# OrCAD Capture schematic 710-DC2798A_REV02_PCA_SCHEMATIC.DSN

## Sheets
1 PAGE1: size Custom; company: ANALOG DEVICES; note: DEMO BOARD BILL OF MATERIALS; note: 60V DUAL PHASE SINGLE OUTPUT SYNCHRONOUS
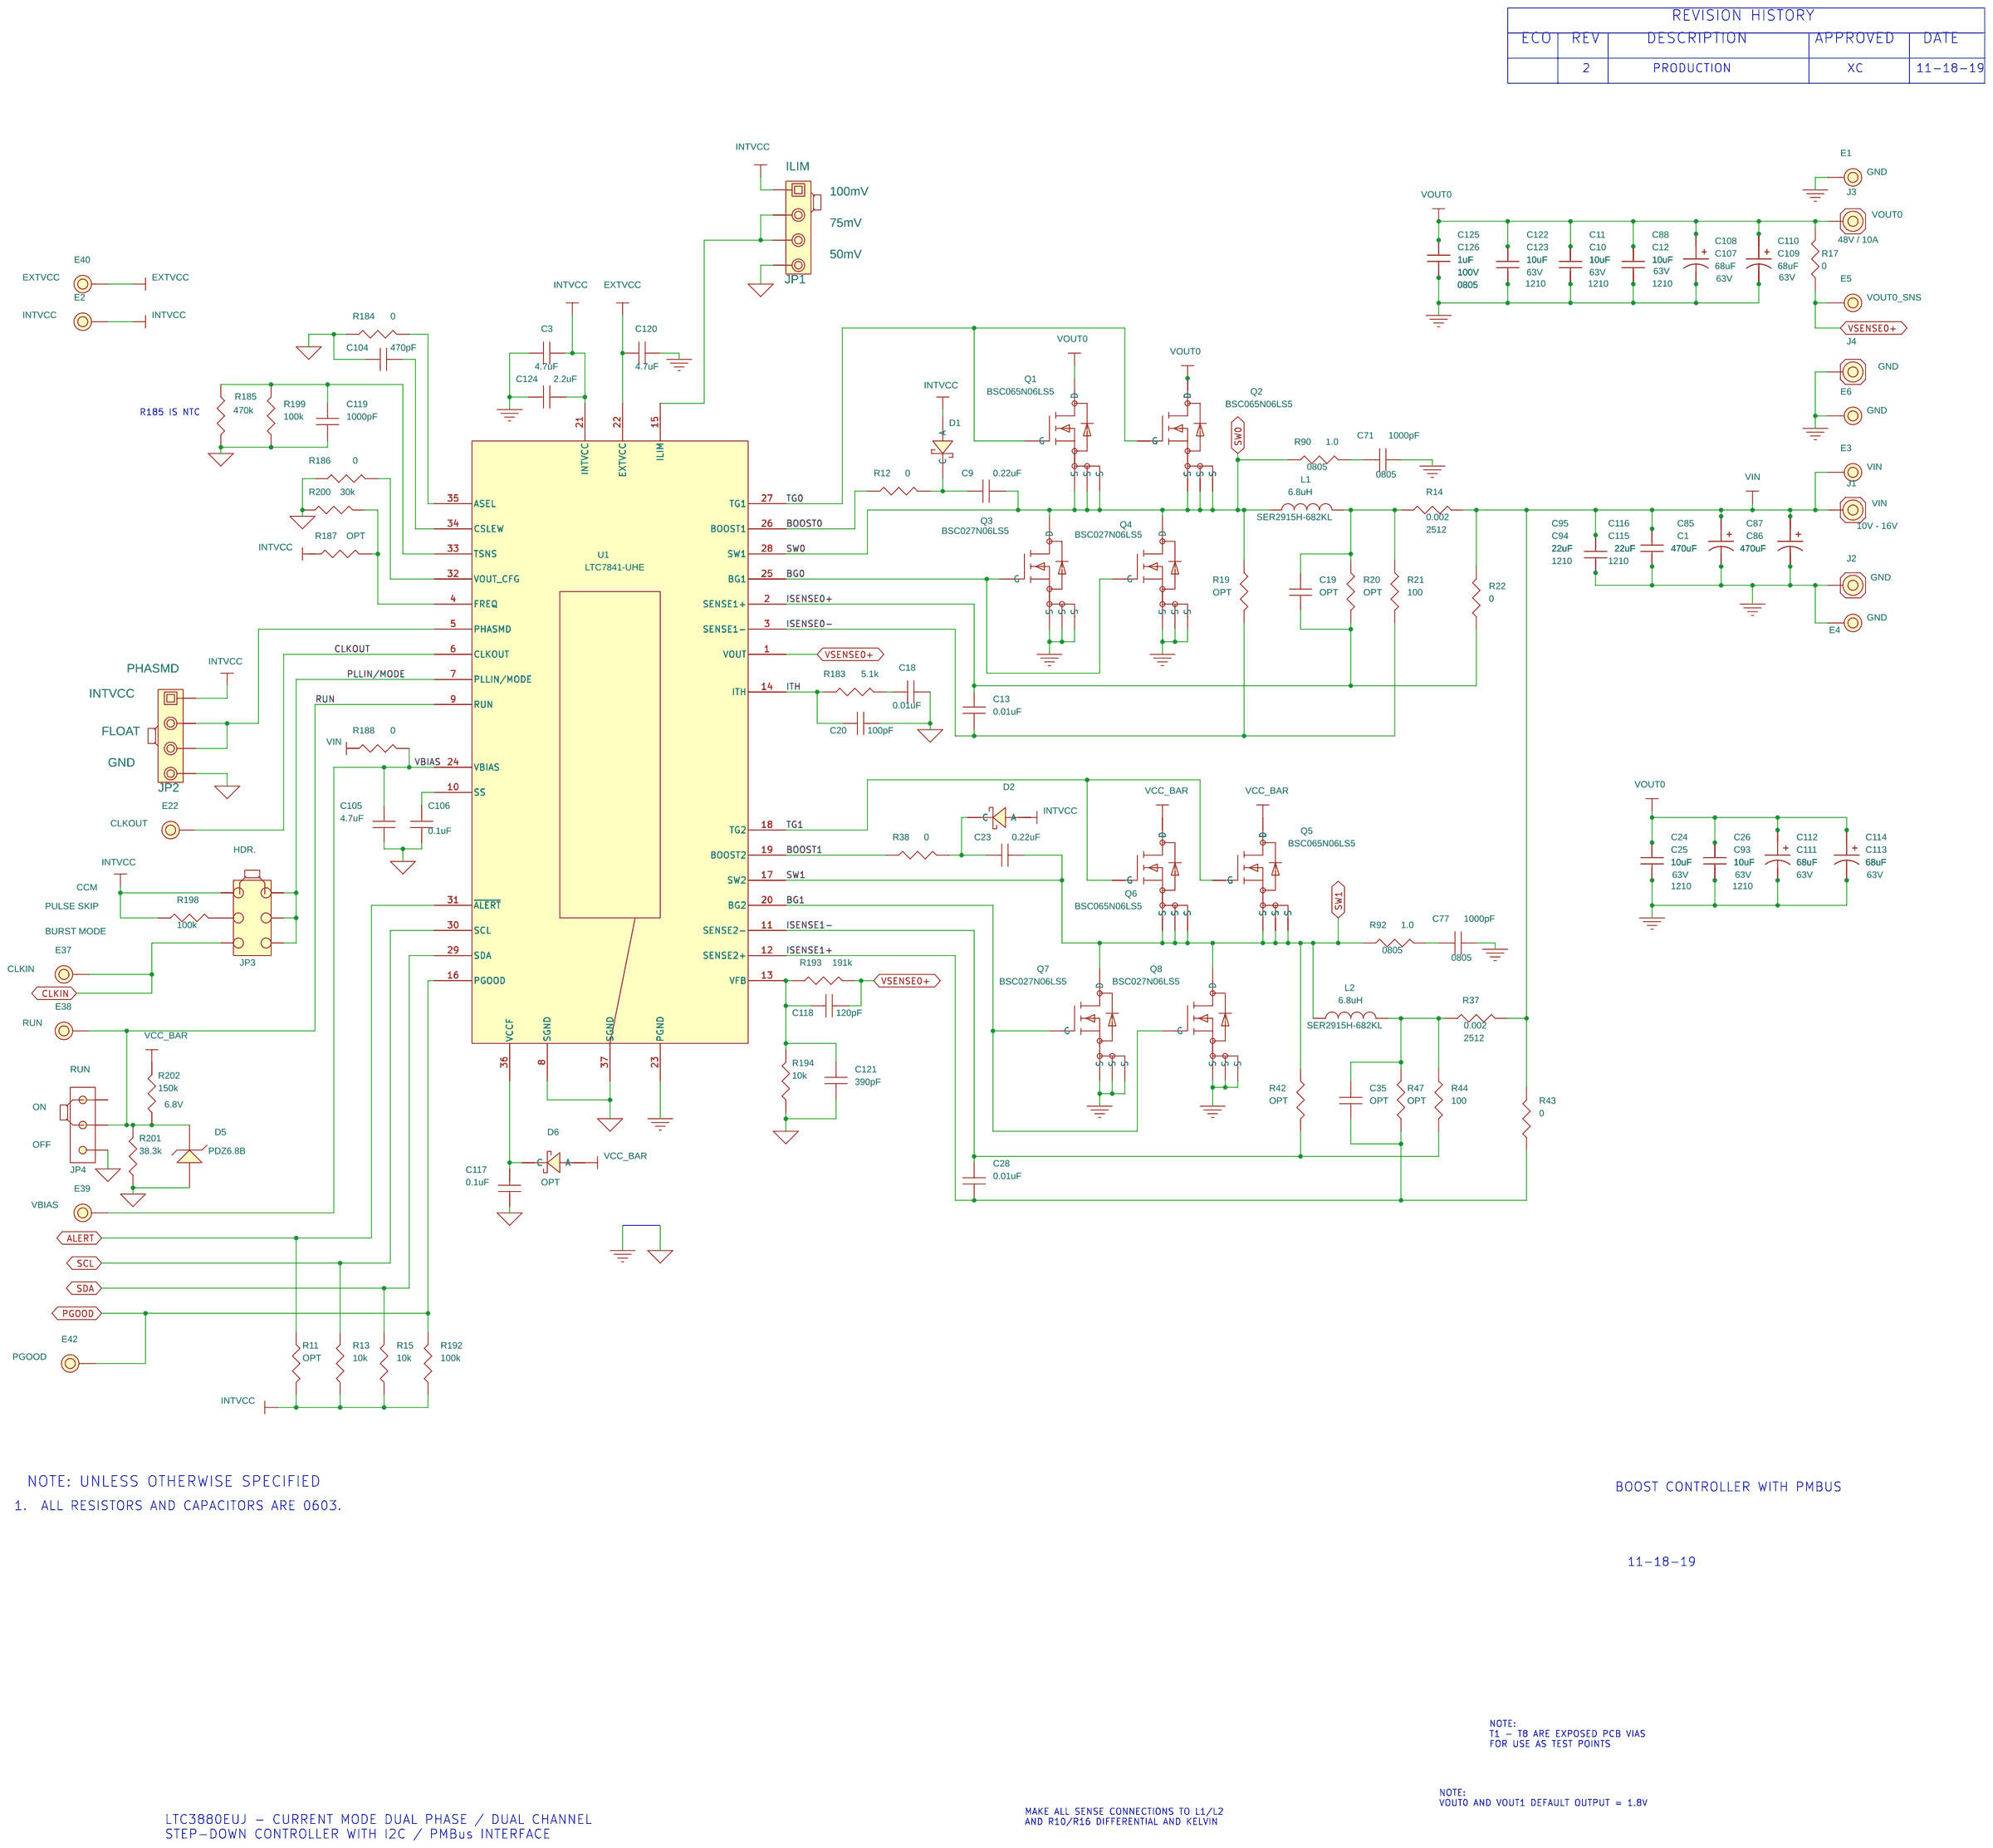
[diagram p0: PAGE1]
2 PAGE2: size Custom
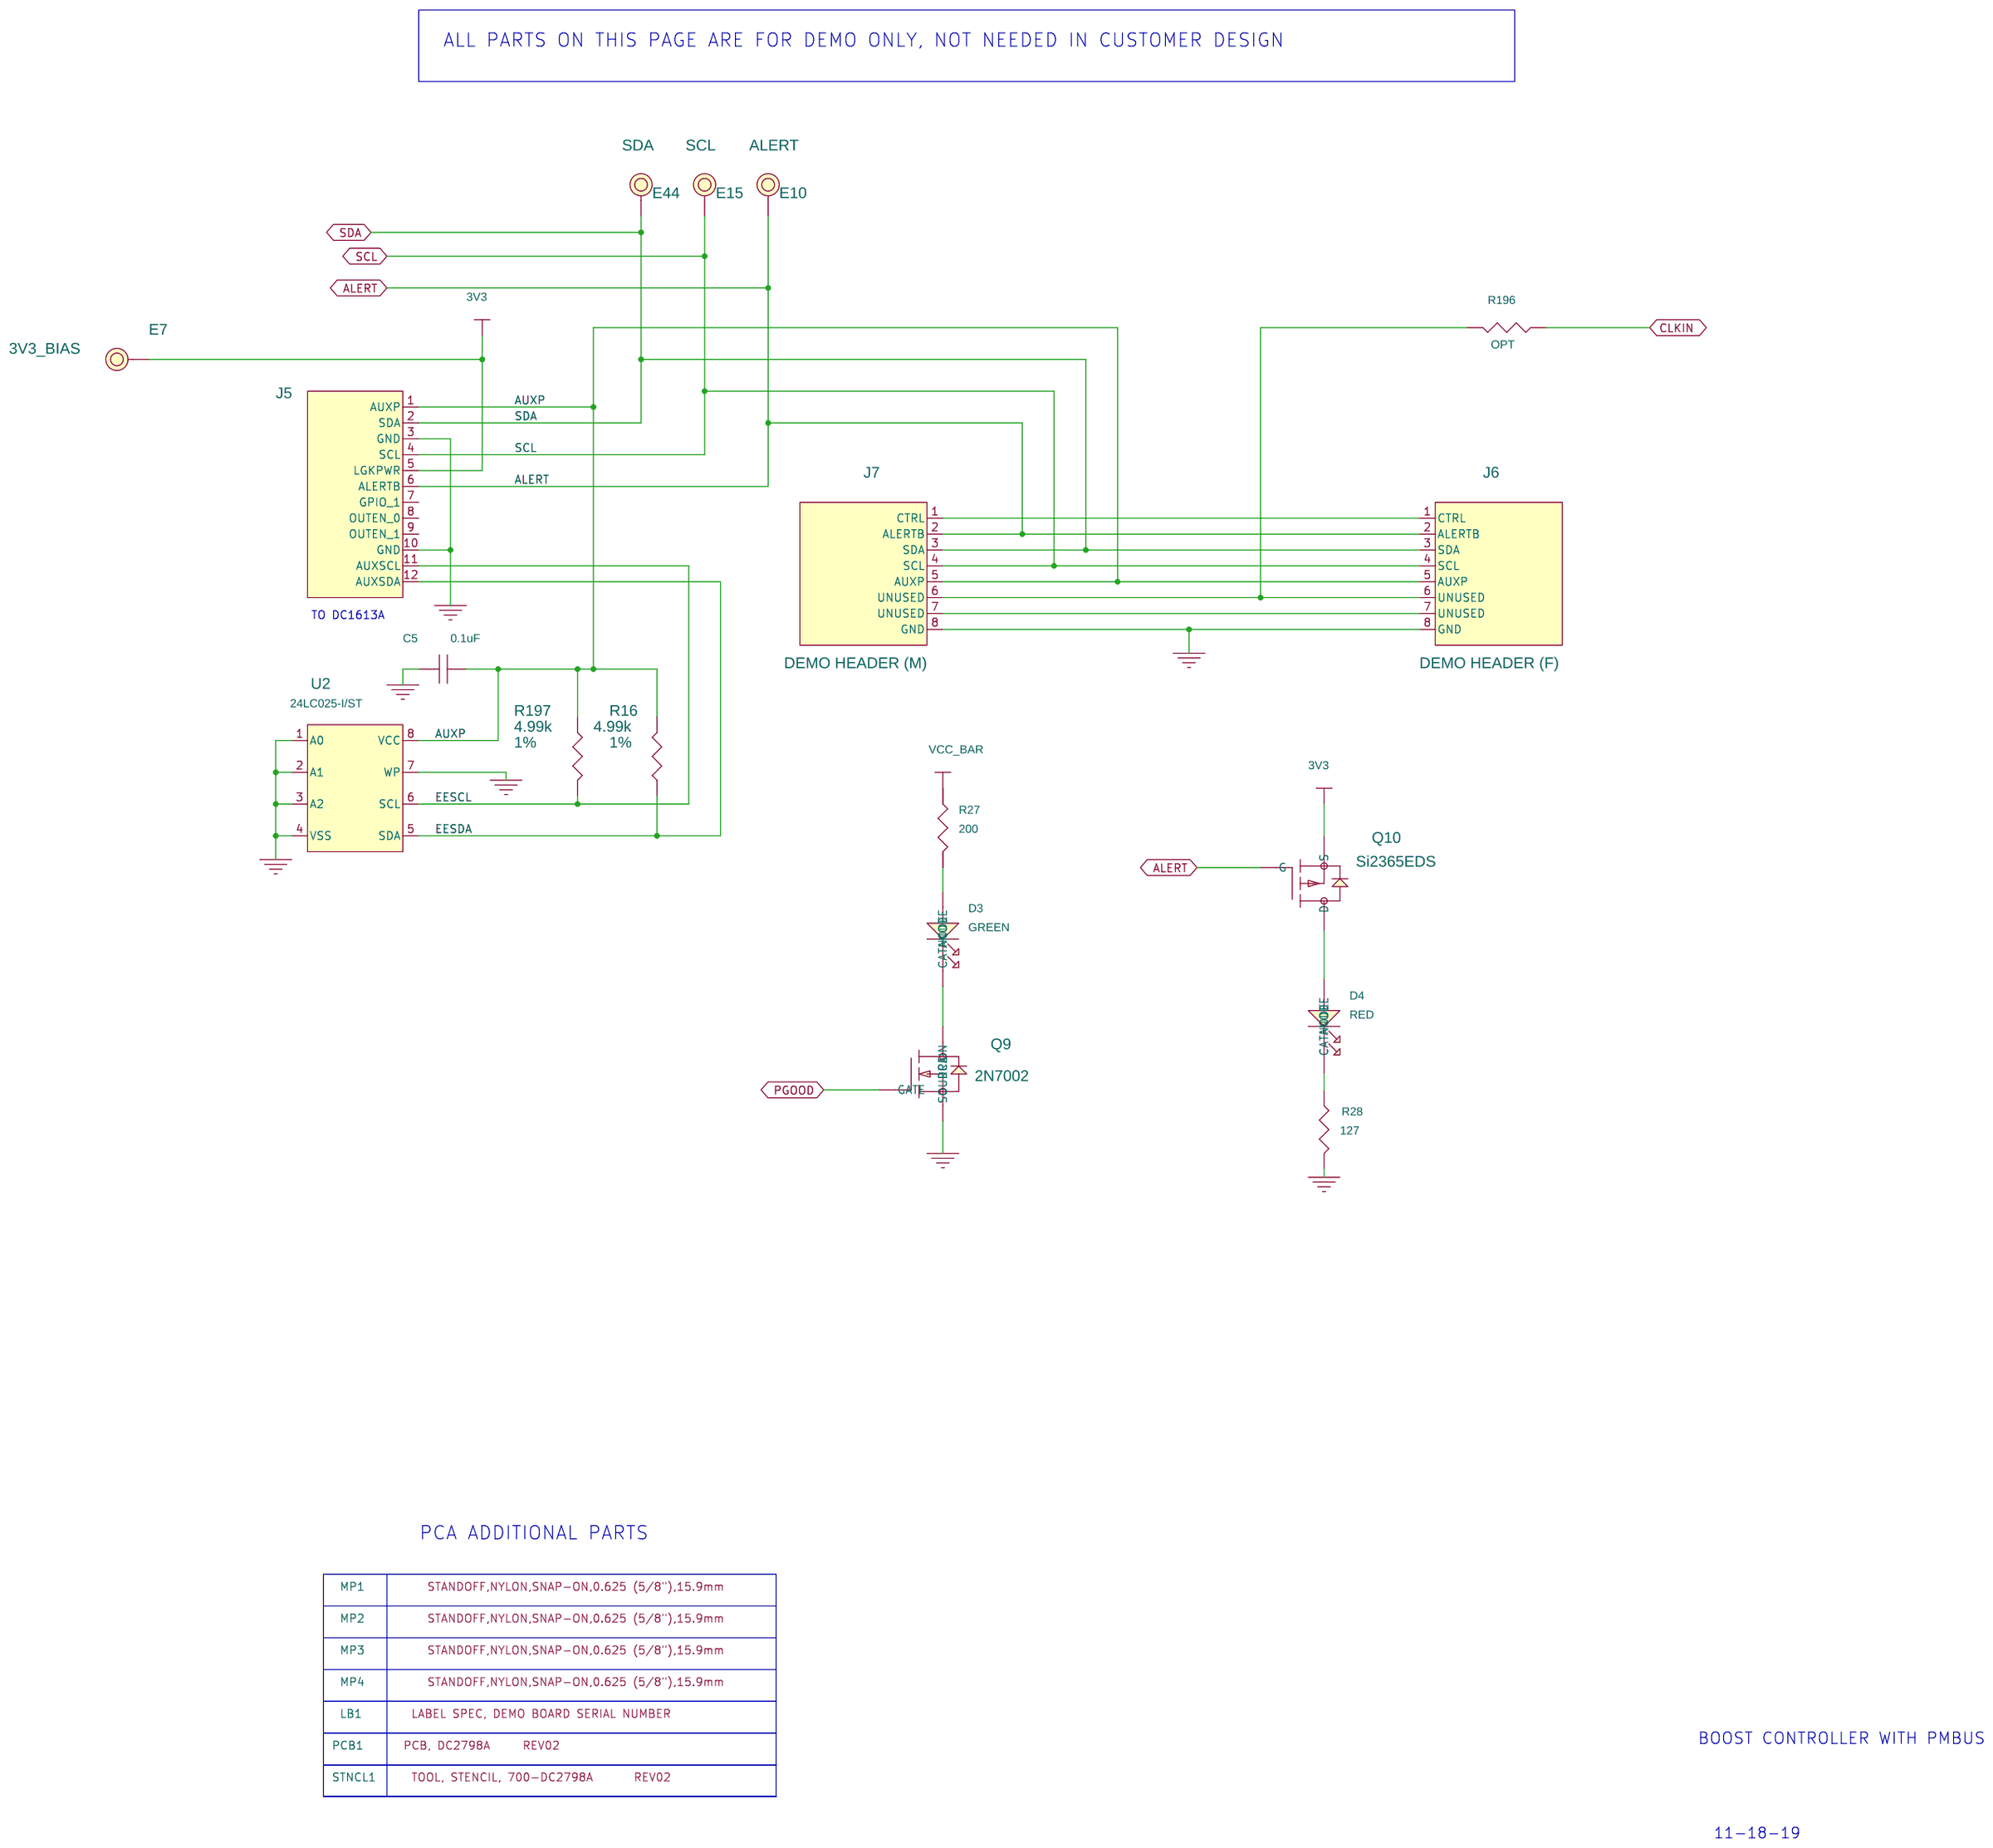
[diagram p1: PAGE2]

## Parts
sheet PAGE1
C1  470uF  [PANASONIC_ZK_10X10.2]
C3  4.7uF  [CC0603N]
C9  0.22uF  [CC0603N]
C10  10uF  [CC1210N]
C11  10uF  [CC1210N]
C12  10uF  [CC1210N]
C13  0.01uF  [CC0603N]
C18  0.01uF  [CC0603N]
C19  OPT  [CC0603N]
C20  100pF  [CC0603N]
C23  0.22uF  [CC0603N]
C24  10uF  [CC1210N]
C25  10uF  [CC1210N]
C26  10uF  [CC1210N]
C28  0.01uF  [CC0603N]
C35  OPT  [CC0603N]
C71  1000pF  [CC0805N]
C77  1000pF  [CC0805N]
C85  470uF  [PANASONIC_ZK_10X10.2]
C86  470uF  [PANASONIC_ZK_10X10.2]
C87  470uF  [PANASONIC_ZK_10X10.2]
C88  10uF  [CC1210N]
C93  10uF  [CC1210N]
C94  22uF  [CC1210N]
C95  22uF  [CC1210N]
C104  470pF  [CC0603N]
C105  4.7uF  [CC0603N]
C106  0.1uF  [CC0603N]
C107  68uF  [PANASONIC_ZC_10X10.2]
C108  68uF  [PANASONIC_ZC_10X10.2]
C109  68uF  [PANASONIC_ZC_10X10.2]
C110  68uF  [PANASONIC_ZC_10X10.2]
C111  68uF  [PANASONIC_ZC_10X10.2]
C112  68uF  [PANASONIC_ZC_10X10.2]
C113  68uF  [PANASONIC_ZC_10X10.2]
C114  68uF  [PANASONIC_ZC_10X10.2]
C115  22uF  [CC1210N]
C116  22uF  [CC1210N]
C117  0.1uF  [CC0603N]
C118  120pF  [CC0603N]
C119  1000pF  [CC0603N]
C120  4.7uF  [CC0603N]
C121  390pF  [CC0603N]
C122  10uF  [CC1210N]
C123  10uF  [CC1210N]
C124  2.2uF  [CC0603N]
C125  1uF  [CC0805N]
C126  1uF  [CC0805N]
D1  DFLS1100  [POWERDI-123]
D2  DFLS1100  [POWERDI-123]
D5  PDZ6.8B  [SOD-323N]
D6  OPT  [POWERDI-123]
E1  TEST POINT  [MILLMAX2501]
E2  TEST POINT  [MILLMAX2501]
E3  TEST POINT  [MILLMAX2501]
E4  TEST POINT  [MILLMAX2501]
E5  TEST POINT  [MILLMAX2501]
E6  TEST POINT  [MILLMAX2501]
E22  TEST POINT  [MILLMAX2501]
E37  TEST POINT  [MILLMAX2501]
E38  TEST POINT  [MILLMAX2501]
E39  TEST POINT  [MILLMAX2501]
E40  TEST POINT  [MILLMAX2501]
E42  TEST POINT  [MILLMAX2501]
J1  STUD,#10-32  [PENN-KFH-032]
J2  STUD,#10-32  [PENN-KFH-032]
J3  STUD,#10-32  [PENN-KFH-032]
J4  STUD,#10-32  [PENN-KFH-032]
JP1  HDR  [HD1X4-079]
JP2  HDR  [HD1X4-079]
JP3  HDR.  [HD2X3-079]
JP4  HDR  [HD1X3-079]
L1  6.8uH  [COILCRAFT-SER2900]
L2  6.8uH  [COILCRAFT-SER2900]
Q1  BSC065N06LS5  [INFINEON-PG-TDSON-8]
Q2  BSC065N06LS5  [INFINEON-PG-TDSON-8]
Q3  BSC027N06LS5  [INFINEON-PG-TDSON-8]
Q4  BSC027N06LS5  [INFINEON-PG-TDSON-8]
Q5  BSC065N06LS5  [INFINEON-PG-TDSON-8]
Q6  BSC065N06LS5  [INFINEON-PG-TDSON-8]
Q7  BSC027N06LS5  [INFINEON-PG-TDSON-8]
Q8  BSC027N06LS5  [INFINEON-PG-TDSON-8]
R11  OPT  [CR0603N]
R12  0  [CR0603N]
R13  10k  [CR0603N]
R14  0.002  [PANASONIC-ERJMS4S]
R15  10k  [CR0603N]
R17  0  [CR0603N]
R19  OPT  [CR0603N]
R20  OPT  [CR0603N]
R21  100  [CR0603N]
R22  0  [CR0603N]
R37  0.002  [PANASONIC-ERJMS4S]
R38  0  [CR0603N]
R42  OPT  [CR0603N]
R43  0  [CR0603N]
R44  100  [CR0603N]
R47  OPT  [CR0603N]
R90  1.0  [CR0805N]
R92  1.0  [CR0805N]
R183  5.1k  [CR0603N]
R184  0  [CR0603N]
R185  470k  [CR0805N]
R186  0  [CR0603N]
R187  OPT  [CR0603N]
R188  0  [CR0603N]
R192  100k  [CR0603N]
R193  191k  [CR0603N]
R194  10k  [CR0603N]
R198  100k  [CR0603N]
R199  100k  [CR0603N]
R200  30k  [CR0603N]
R201  38.3k  [CR0603N]
R202  150k  [CR0603N]
U1  LTC7841-UHE  [LTC-UHE-36-1876]
XJP2  SHUNT
XJP7  SHUNT
XJP8  SHUNT
XJP9  SHUNT
sheet PAGE2
C5  0.1uF  [CC0603N]
D3  GREEN  [LED_1206]
D4  RED  [LED_1206]
E7  TEST POINT  [MILLMAX2501]
E10  TEST POINT  [MILLMAX2501]
E15  TEST POINT  [MILLMAX2501]
E44  TEST POINT  [MILLMAX2501]
J5  HDR,SHROUDED  [HD2X6-079-MOLEX]
J6  HDR  [SULLINS-NPPN042FJFN-RC]
J7  HDR  [MOLEX-87760-0816]
LB1  LABEL  [895-0154_REV01]
MP1  STANDOFF  [KEYSTONE_8829-8834]
MP2  STANDOFF  [KEYSTONE_8829-8834]
MP3  STANDOFF  [KEYSTONE_8829-8834]
MP4  STANDOFF  [KEYSTONE_8829-8834]
PCB1  PCB, DC2798A
Q9  2N7002  [SOT23-3N]
Q10  Si2365EDS  [SOT23-3N]
R16  4.99k  [CR0603N]
R27  200  [CR0603N]
R28  127  [CR0603N]
R196  OPT  [CR0603N]
R197  4.99k  [CR0603N]
STNCL1  TOOL, STENCIL, 700-DC2798A
U2  24LC025-I/ST  [MICROCHIP-TSSOP-8]

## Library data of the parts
C1 C85-C87 = CAP_P: CAP.,470uF,ALUM POLY HYB,25V,20%,10x10.2mm,G,SMD,RADIAL,AEC-Q200; CLASS: DISCRETE; Dielectric Type: ALUM POLY HYB; Inventory Qty: 1000; Manufacturer: PANASONIC; Manufacturer PN: EEHZK1E471P; PART_NUMBER: 150-2512; Package Size: 10x10.2mm,G,SMD,RADIAL; Rated Voltage: 25V; Tolerance: 20%; UserField01: AEC-Q200
C3 C105 C120 = CAP: CAP.,4.7uF,X5R,25V,10%,0603; CLASS: DISCRETE; Dielectric Type: X5R; FPLIST: CC0603N,CC0603L,CC0603M; Inventory Qty: 10126; Manufacturer: MURATA; Manufacturer PN: GRM188R61E475KE15D; PART_NUMBER: 150-0445; Package Size: 0603; Rated Voltage: 25V; Tolerance: 10%
C9 C23 = CAP: CAP.,0.22uF,X7R,25V,10%,0603; CLASS: DISCRETE; Dielectric Type: X7R; FPLIST: CC0603N,CC0603L,CC0603M; Inventory Qty: 20653; Manufacturer: MURATA; Manufacturer PN: GRM188R71E224KA88D; PART_NUMBER: 150-0320; Package Size: 0603; Rated Voltage: 25V; Tolerance: 10%
C10-C12 C24-C26 C88 C93 C122 C123 = CAP: CAP.,10uF,X7R,63V,10%,1210; CLASS: DISCRETE; Component: cap; Dielectric Type: X7R; FPLIST: CC1210N,CC1210L,CC1210M; Inventory Qty: 5452; Manufacturer: Murata; Manufacturer PN: GRM32ER71J106KA12L; PART_NUMBER: 150-1321; Package Size: 1210; Part Type: CAP1210; Rated Voltage: 63V; Tolerance: 10%
C13 C28 = CAP: CAP.,0.01uF,X7R,16V,10%,0603; CLASS: DISCRETE; Component: cap; Dielectric Type: X7R; FPLIST: CC0603N,CC0603L,CC0603M; Inventory Qty: 69027; Manufacturer: AVX; Manufacturer PN: 0603YC103KAT2A; PART_NUMBER: 150-0038; Package Size: 0603; Rated Voltage: 16V; Tolerance: 10%
C18 = CAP: CAP.,0.01uF,X7R,25V,10%,0603,AEC-Q200; CLASS: DISCRETE; Component: cap; Dielectric Type: X7R; FPLIST: CC0603N,CC0603L,CC0603M; Inventory Qty: 47182; Manufacturer: AVX; Manufacturer PN: 06033C103K4Z2A; PART_NUMBER: 150-0440; Package Size: 0603; Rated Voltage: 25V; Tolerance: 10%
C19 C35 = CAP: CAP., OPTION, 0603; CLASS: DISCRETE; FPLIST: CC0603N,CC0603L,CC0603M; PART_NUMBER: 150-3038; Package Size: 0603; Package Type: SMD; UserField01: OPTION
C20 = CAP: CAP.,100pF,C0G/NP0,50V,5%,0603; CLASS: DISCRETE; Component: cap; Dielectric Type: C0G/NP0; FPLIST: CC0603N,CC0603L,CC0603M; Inventory Qty: 27408; Manufacturer: AVX; Manufacturer PN: 06035A101JAT2A; PART_NUMBER: 150-3145; Package Size: 0603; Rated Voltage: 50V; Tolerance: 5%
C71 C77 = CAP: CAP.,1000pF,C0G,100V,5%,0805; CLASS: DISCRETE; Dielectric Type: C0G; Inventory Qty: 0; Manufacturer: MURATA; Manufacturer PN: GRM2195C2A102JA01D; PART_NUMBER: 150-0816; Package Size: 0805; Package Type: SMD/SMT; Rated Voltage: 100V; Tolerance: 5%
C94 C95 C115 C116 = CAP: CAP.,22uF,X7R,25V,10%,1210; CLASS: DISCRETE; Component: cap; Dielectric Type: X7R; FPLIST: CC1210N,CC1210L,CC1210M; Inventory Qty: 4160; Manufacturer: SAMSUNG; Manufacturer PN: CL32B226KAJNNNE; PART_NUMBER: 150-3233; Package Size: 1210; Rated Voltage: 25V; Tolerance: 10%
C104 = CAP: CAP.,470pF,X7R,50V,10%,0603; CLASS: DISCRETE; Dielectric Type: X7R; FPLIST: CC0603N,CC0603L,CC0603M; Inventory Qty: 25212; Manufacturer: AVX; Manufacturer PN: 06035C471KAT2A; PART_NUMBER: 150-0125; Package Size: 0603; Rated Voltage: 50V; Tolerance: 10%; UserField01: OPTION
C106 C117 = CAP: CAP.,0.1uF,X7R,100V,10%,0603; CLASS: DISCRETE; Component: cap; Dielectric Type: X7R; FPLIST: CC0603N,CC0603L,CC0603M; Inventory Qty: 37708; Manufacturer: AVX; Manufacturer PN: 06031C104KAT2A; PART_NUMBER: 150-3294; Package Size: 0603; Rated Voltage: 100V; Tolerance: 10%
C107-C114 = CAP_P: CAP.,68uF,ALUM POLY HYB,63V,20%,10x10.2mm,G,SMD,RADIAL,AEC-Q200; CLASS: DISCRETE; Dielectric Type: ALUM POLY HYB; Inventory Qty: 4000; Manufacturer: PANASONIC; Manufacturer PN: EEHZC1J680P; PART_NUMBER: 150-2511; Package Size: 10x10.2mm,G,SMD,RADIAL; Rated Voltage: 63V; Tolerance: 20%; UserField01: AEC-Q200
C118 = CAP: CAP.,120PF,C0G/NPO,100V,5%,0603; CLASS: DISCRETE; Dielectric Type: C0G; Inventory Qty: 0; Manufacturer: AVX; Manufacturer PN: 06031A121JAT2A; PART_NUMBER: 150-0828; Package Size: 0603; Rated Voltage: 100V; Tolerance: 5%
C119 = CAP: CAP.,1000pF,X7R,16V,10%,0603; CLASS: DISCRETE; Component: cap; Dielectric Type: X7R; FPLIST: CC0603N,CC0603L,CC0603M; Inventory Qty: 1618; Manufacturer: WURTH ELEKTRONIK; Manufacturer PN: 885012206034; PART_NUMBER: 150-2357; Package Size: 0603; Rated Voltage: 16V; Tolerance: 10%
C121 = CAP: CAP.,390pF,COG/NPO,50V,5%,0603; CLASS: DISCRETE; Dielectric Type: C0G; Inventory Qty: 0; Manufacturer: AVX; Manufacturer PN: 06035A391JAT2A; PART_NUMBER: 150-0829; Package Size: 0603; Rated Voltage: 50V; Tolerance: 5%
C124 = CAP: CAP.,2.2uF,X7S,16V,10%,0603,AEC-Q200; CLASS: DISCRETE; Dielectric Type: X7S; FPLIST: CC0603N,CC0603L,CC0603M; Inventory Qty: 3469; Manufacturer: TDK; Manufacturer PN: CGA3E1X7S1C225K080AC; PART_NUMBER: 150-1663; Package Size: 0603; Package Type: Surface Mount, MLCC; Rated Voltage: 16V; Temperature Coefficient: X7S; Tolerance: 10%
C125 C126 = CAP: CAP.,1uF,X7S,100V,10%,0805; CLASS: DISCRETE; Component: cap; Dielectric Type: X7S; FPLIST: CC0805N,CC0805L,CC0805M; Inventory Qty: 17806; Manufacturer: MURATA; Manufacturer PN: GRJ21BC72A105KE11L; PART_NUMBER: 150-3382; Package Size: 0805; Rated Voltage: 100V; Tolerance: 10%
D1 D2 = DIODE_SCHOTTKY_A: DIODE,SCHOTTKY,100V,1A,POWERDI-123; CLASS: DISCRETE; Component: diode; Inventory Qty: 14646; Manufacturer: DIODES INC.; Manufacturer PN: DFLS1100-7; Max Forward Current or Rated Power: 1A; PART_NUMBER: 210-0044; Package Size: POWERDI®123; Rated Voltage: 100V; Rated Voltage or Zener Voltage: 100V
D5 = ZENER_ALT: DIODE,ZENER,6.8V,400mW,SOD-323; CLASS: DISCRETE; FPLIST: SOD-323N,SOD-323L,SOD-323M; Inventory Qty: 3630; Manufacturer: NEXPERIA; Manufacturer PN: PDZ6.8B,115; Max Forward Current or Rated Power: 400mW; PART_NUMBER: 210-0317; Package Type: SOD-323; Rated Voltage: 6.8V; Rated Voltage or Zener Voltage: 6.8V
D6 = DIODE_SCHOTTKY_A: DIODE, OPTION, SCHOTTKY, POWERDI 123; CLASS: DISCRETE; Component: diode; PART_NUMBER: 210-0341; Package Type: PowerDI 123; Rated Voltage: 100V
E1 E4 E6 = TESTPOINT_.219_MILL-MAX_2501: TEST POINT,TURRET,0.094" MTG. HOLE,PCB 0.062" THK; CLASS: IO; Inventory Qty: 416229; Manufacturer: MILL-MAX; Manufacturer PN: 2501-2-00-80-00-00-07-0; PART_FIELD_01: GND; PART_NUMBER: 260-0003
E2 = TESTPOINT_.219_MILL-MAX_2501: TEST POINT,TURRET,0.094" MTG. HOLE,PCB 0.062" THK; CLASS: IO; Inventory Qty: 416229; Manufacturer: MILL-MAX; Manufacturer PN: 2501-2-00-80-00-00-07-0; PART_FIELD_01: INTVCC; PART_NUMBER: 260-0003
E3 = TESTPOINT_.219_MILL-MAX_2501: TEST POINT,TURRET,0.094" MTG. HOLE,PCB 0.062" THK; CLASS: IO; Inventory Qty: 416229; Manufacturer: MILL-MAX; Manufacturer PN: 2501-2-00-80-00-00-07-0; PART_FIELD_01: VIN; PART_NUMBER: 260-0003
E5 = TESTPOINT_.219_MILL-MAX_2501: TEST POINT,TURRET,0.094" MTG. HOLE,PCB 0.062" THK; CLASS: IO; Inventory Qty: 416229; Manufacturer: MILL-MAX; Manufacturer PN: 2501-2-00-80-00-00-07-0; PART_FIELD_01: VOUT0_SNS; PART_NUMBER: 260-0003
E22 = TESTPOINT_.219_MILL-MAX_2501: TEST POINT,TURRET,0.094" MTG. HOLE,PCB 0.062" THK; CLASS: IO; Inventory Qty: 416229; Manufacturer: MILL-MAX; Manufacturer PN: 2501-2-00-80-00-00-07-0; PART_FIELD_01: CLKOUT; PART_NUMBER: 260-0003
E37 = TESTPOINT_.219_MILL-MAX_2501: TEST POINT,TURRET,0.094" MTG. HOLE,PCB 0.062" THK; CLASS: IO; Inventory Qty: 416229; Manufacturer: MILL-MAX; Manufacturer PN: 2501-2-00-80-00-00-07-0; PART_FIELD_01: CLKIN; PART_NUMBER: 260-0003
E38 = TESTPOINT_.219_MILL-MAX_2501: TEST POINT,TURRET,0.094" MTG. HOLE,PCB 0.062" THK; CLASS: IO; Inventory Qty: 416229; Manufacturer: MILL-MAX; Manufacturer PN: 2501-2-00-80-00-00-07-0; PART_FIELD_01: RUN; PART_NUMBER: 260-0003
E39 = TESTPOINT_.219_MILL-MAX_2501: TEST POINT,TURRET,0.094" MTG. HOLE,PCB 0.062" THK; CLASS: IO; Inventory Qty: 416229; Manufacturer: MILL-MAX; Manufacturer PN: 2501-2-00-80-00-00-07-0; PART_FIELD_01: VBIAS; PART_NUMBER: 260-0003
E40 = TESTPOINT_.219_MILL-MAX_2501: TEST POINT,TURRET,0.094" MTG. HOLE,PCB 0.062" THK; CLASS: IO; Inventory Qty: 416229; Manufacturer: MILL-MAX; Manufacturer PN: 2501-2-00-80-00-00-07-0; PART_FIELD_01: EXTVCC; PART_NUMBER: 260-0003
E42 = TESTPOINT_.219_MILL-MAX_2501: TEST POINT,TURRET,0.094" MTG. HOLE,PCB 0.062" THK; CLASS: IO; Inventory Qty: 416229; Manufacturer: MILL-MAX; Manufacturer PN: 2501-2-00-80-00-00-07-0; PART_FIELD_01: PGOOD; PART_NUMBER: 260-0003
J1 = PEM-KFH: EVAL BOARD STUD HARDWARE SET, #10-32; 10th Part Field: 10V - 16V; 11th Part Field: 11th???; 9th Part Field: VIN; CLASS: DISCRETE; Comments: CONSISTS OF QTY(1) STUD, 769-0012; QTY(1) RING LUG, 769-0013;QTY(2) HEX NUT,BRASS,761-0013; QTY(1) WASHER,#10 LOCK, 762-0021; Manufacturer: ANALOG DEVICES; Manufacturer PN: 720-0010; PART_NUMBER: 720-0010
J2 = PEM-KFH: EVAL BOARD STUD HARDWARE SET, #10-32; 10th Part Field: 5 - 24V #; 11th Part Field: 11th???; 9th Part Field: GND; CLASS: DISCRETE; Comments: CONSISTS OF QTY(1) STUD, 769-0012; QTY(1) RING LUG, 769-0013;QTY(2) HEX NUT,BRASS,761-0013; QTY(1) WASHER,#10 LOCK, 762-0021; Manufacturer: ANALOG DEVICES; Manufacturer PN: 720-0010; PART_NUMBER: 720-0010
J3 = PEM-KFH: EVAL BOARD STUD HARDWARE SET, #10-32; 10th Part Field: 48V / 10A; 11th Part Field: 11th???; 9th Part Field: VOUT0; CLASS: DISCRETE; Comments: CONSISTS OF QTY(1) STUD, 769-0012; QTY(1) RING LUG, 769-0013;QTY(2) HEX NUT,BRASS,761-0013; QTY(1) WASHER,#10 LOCK, 762-0021; Manufacturer: ANALOG DEVICES; Manufacturer PN: 720-0010; PART_NUMBER: 720-0010
J4 = PEM-KFH: EVAL BOARD STUD HARDWARE SET, #10-32; 9th Part Field: GND; CLASS: DISCRETE; Comments: CONSISTS OF QTY(1) STUD, 769-0012; QTY(1) RING LUG, 769-0013;QTY(2) HEX NUT,BRASS,761-0013; QTY(1) WASHER,#10 LOCK, 762-0021; Manufacturer: ANALOG DEVICES; Manufacturer PN: 720-0010; PART_NUMBER: 720-0010
JP1 = HDR1X4_ALT1: CONN.,HDR,MALE,1x4,2mm,VERT,ST,THT; 11th Part Field: 75mV; 12th Part Field: ILIM; 4th Part Field: 100mV; 5th Part Field: ON1_CONTROL; 9th Part Field: 50mV; CLASS: IO; FPLIST: HD1X4-079,JP4X1/079; Inventory Qty: 8742; Manufacturer: SAMTEC; Manufacturer PN: TMM-104-02-L-S; PART_NUMBER: 250-0441
JP2 = HDR1X4_ALT1: CONN.,HDR,MALE,1x4,2mm,VERT,ST,THT; 11th Part Field: FLOAT; 12th Part Field: PHASMD; 4th Part Field: GND; 5th Part Field: ON1_CONTROL; 9th Part Field: INTVCC; CLASS: IO; FPLIST: HD1X4-079,JP4X1/079; Inventory Qty: 8742; Manufacturer: SAMTEC; Manufacturer PN: TMM-104-02-L-S; PART_NUMBER: 250-0441
JP3 = HEADER_2X3_.079: CONN.,HDR.,MALE,2x3,2mm,VERT,ST,THT; CLASS: IO; Inventory Qty: 16324; L2: PULSE SKIP; L3: BURST MODE; LABEL1: CCM; Manufacturer: WURTH ELEKTRONIK; Manufacturer PN: 62000621121; PART_NUMBER: 250-0483
JP4 = 3_PIN_HEADER_.079_SINGLE_ROW_C: CONN.,HDR,MALE,1x3,2mm,VERT,ST,THT; CLASS: IO; Inventory Qty: 25420; LABEL1: RUN; LBL2: ON; LBL3: OFF; Manufacturer: Wurth Elektronik; Manufacturer PN: 62000311121; PART_NUMBER: 250-0484
L1 L2 = IND_ALT: IND.,6.8uH,Power Shielded Wirewound,10%,30A,0.00205 OHMS,27.9mm X 27.94mm; CLASS: DISCRETE; FPLIST: COILCRAFT-SER29XX-N,COILCRAFT-SER29XX-L,COILCRAFT-SER29XX-M; Inventory Qty: 0; Manufacturer: COILCRAFT; Manufacturer PN: SER2915H-682KL; PART_NUMBER: 200-0721; Package Size: 27.9mm X 27.94mm; Tolerance: 10%
Q1 Q2 Q5 Q6 = 5P_N-CH_TYPE1C: XSTR.,MOSFET, N-CH,60V,64A,PG-TDSON-8; CLASS: DISCRETE; Inventory Qty: 5800; Manufacturer: INFINEON; PART_NUMBER: 240-0322; Package Size: PG-TDSON8; Package Type: PG-TDSON-8; Rated Voltage: 60V
Q3 Q4 Q7 Q8 = 5P_N-CH_TYPE1C: XSTR.,MOSFET, N-CH,60V,100A,PG-TDSON-8; CLASS: DISCRETE; Inventory Qty: 9532; Manufacturer: INFINEON; PART_NUMBER: 240-0323; Package Size: PG-TDSON8; Package Type: PG-TDSON-8; Rated Voltage: 60V
R11 R19 R20 R42 R47 = RES: RES., OPTION, 0603; CLASS: DISCRETE; FPLIST: CR0603N,CR0603L,CR0603M; PART_NUMBER: 100-2374; Package Size: 0603
R12 R17 R22 R38 R43 R184 = RES: RES.,0 OHM,1/10W,0603,AEC-Q200; CLASS: DISCRETE; FPLIST: CR0603N,CR0603L,CR0603M; Inventory Qty: 651730; Manufacturer: VISHAY; Manufacturer PN: CRCW06030000Z0EA; PART_NUMBER: 100-0009; Package Size: 0603; Rated Power: 1/10W
R13 R15 = RES: RES.,10k OHMS,1%,1/10W,0603; CLASS: DISCRETE; FPLIST: CR0603N,CR0603L,CR0603M; Inventory Qty: 73157; Manufacturer: VISHAY; Manufacturer PN: CRCW060310K0FKEC; PART_NUMBER: 100-2532; Package Size: 0603; Part Type: CR0402; Rated Power: 1/10W; Temperature Coefficient: 100ppm/C; Tolerance: 1%
R14 R37 = RES: RES.,0.002 OHM,1%,3W,2512,METAL,SENSE,AEC-Q200; CLASS: DISCRETE; Component: res; FPLIST: CR2512N,CR2512L,CR2512M; Inventory Qty: 4000; Manufacturer: PANASONIC; Manufacturer PN: ERJMS4SF2M0U; PART_NUMBER: 100-1347; Package Size: 2512; Rated Power: 3W; Temperature Coefficient: +/-75ppm; Tolerance: 1%
R21 R44 = RES: RES.,100 OHMS,1%,1/10W,0603,AEC-Q200; CLASS: DISCRETE; Component: res; FPLIST: CR0603N,CR0603L,CR0603M; Inventory Qty: 70759; Manufacturer: PANASONIC; Manufacturer PN: ERJ3EKF1000V; PART_NUMBER: 100-2586; Package Size: 0603; Rated Power: 1/10W; Temperature Coefficient: 100ppm; Tolerance: 1%
R90 R92 = RES: RES.,1.0 OHMS,5%,1/2W,0805; CLASS: DISCRETE; Inventory Qty: 5000; Manufacturer: PANASONIC; Manufacturer PN: ERJ6DQJ1R0V; PART_NUMBER: 100-1618; Package Size: 0805; Rated Power: 1/2W; Temperature Coefficient: +/-100; Tolerance: 5%
R183 = RES: RES.,5.1k OHMS,1%,1/10W,0603,AEC-Q200; CLASS: DISCRETE; FPLIST: CR0603N,CR0603L,CR0603M; Inventory Qty: 29594; Manufacturer: NIC; Manufacturer PN: NRC06F5101TRF; PART_NUMBER: 100-0491; Package Size: 0603; Part Type: CR0402; Rated Power: 1/10W; Temperature Coefficient: 100ppm; Tolerance: 1%
R185 = RES: RES.,470k OHMS,1%,210mW,0805,NTC THERMISTOR, AEC-Q200; CLASS: DISCRETE; Inventory Qty: 4000; Manufacturer: VISHAY; Manufacturer PN: NTCS0805E3474FXT; PART_NUMBER: 100-1006; Package Size: 0805; Rated Power: 210mW; Tolerance: 1%
R186 R188 = RES: RES.,0 OHM,1/10W,0603,AEC-Q200; CLASS: DISCRETE; FPLIST: CR0603N,CR0603L,CR0603M; Inventory Qty: 651730; Manufacturer: VISHAY; Manufacturer PN: CRCW06030000Z0EA; PART_NUMBER: 100-0009; Package Size: 0603; Part Type: CR0402; Rated Power: 1/10W
R187 = RES: RES., OPTION, 0603; CLASS: DISCRETE; FPLIST: CR0603N,CR0603L,CR0603M; PART_NUMBER: 100-2374; Package Size: 0603; Part Type: CR0402
R192 = RES: RES.,100k OHMS,1%,1/10W,0603,AEC-Q200; CLASS: DISCRETE; FPLIST: CR0603N,CR0603L,CR0603M; Inventory Qty: 184622; Manufacturer: VISHAY; Manufacturer PN: CRCW0603100KFKEA; PART_NUMBER: 100-0343; Package Size: 0603; Part Type: CR0402; Rated Power: 1/10W; Temperature Coefficient: +/-100ppm; Tolerance: 1%
R193 = RES: RES.,191k OHMS,1%,1/10W,0603; CLASS: DISCRETE; FPLIST: CR0603N,CR0603L,CR0603M; Inventory Qty: 34432; Label: 0; Manufacturer: VISHAY; Manufacturer PN: CRCW0603191KFKEA; PART_NUMBER: 100-2371; Package Size: 0603; Rated Power: 1/10W; Temperature Coefficient: +/-100ppm; Tolerance: 1%
R194 = RES: RES.,10k OHMS,1%,1/10W,0603; CLASS: DISCRETE; FPLIST: CR0603N,CR0603L,CR0603M; Inventory Qty: 73157; Label: 0; Manufacturer: VISHAY; Manufacturer PN: CRCW060310K0FKEC; PART_NUMBER: 100-2532; Package Size: 0603; Rated Power: 1/10W; Temperature Coefficient: 100ppm/C; Tolerance: 1%
R198 R199 = RES: RES.,100k OHMS,1%,1/10W,0603,AEC-Q200; CLASS: DISCRETE; FPLIST: CR0603N,CR0603L,CR0603M; Inventory Qty: 184622; Manufacturer: VISHAY; Manufacturer PN: CRCW0603100KFKEA; PART_NUMBER: 100-0343; Package Size: 0603; Rated Power: 1/10W; Temperature Coefficient: +/-100ppm; Tolerance: 1%
R200 = RES: RES.,30k OHMS,1%,1/10W,0603,AEC-Q200; CLASS: DISCRETE; FPLIST: CR0603N,CR0603L,CR0603M; Inventory Qty: 19400; Manufacturer: KOA SPEER; Manufacturer PN: RK73H1JTTD3002F; PART_NUMBER: 100-2436; Package Size: 0603; Part Type: CR0402; Rated Power: 1/10W; Temperature Coefficient: 100ppm/C; Tolerance: 1%
R201 = RES: RES.,38.3k OHMS,1%,1/10W,0603,AEC-Q200; CLASS: DISCRETE; FPLIST: CR0603N,CR0603L,CR0603M; Inventory Qty: 32568; Label: 0; Manufacturer: NIC; Manufacturer PN: NRC06F3832TRF; PART_NUMBER: 100-2656; Package Size: 0603; Rated Power: 1/10W; Temperature Coefficient: 100ppm/C; Tolerance: 1%
R202 = RES: RES.,150k OHMS,1%,1/10W,0603; CLASS: DISCRETE; FPLIST: CR0603N,CR0603L,CR0603M; Inventory Qty: 37924; Label: 0; Manufacturer: PANASONIC; Manufacturer PN: ERJ3EKF1503V; PART_NUMBER: 100-2438; Package Size: 0603; Rated Power: 1/10W; Temperature Coefficient: 100ppm/C; Tolerance: 1%
U1 = LTC7841-UHE: IC,POWER CONTROLLER,QFN-36 (5x6); CLASS: IC; Inventory Qty: 0; Manufacturer: LINEAR TECH.; Manufacturer PN: LTC7841EUHE#PBF; PART_NUMBER: LTC7841EUHE#PBF; Package Size: 36QFN-5X6MM; Package Type: QFN-36 (5x6)
XJP2 XJP7-XJP9 = SHUNT_2MM: CONN.,SHUNT,FEMALE,2-POS,2mm; CLASS: IO; Inventory Qty: 84501; Manufacturer: SAMTEC; Manufacturer PN: 2SN-BK-G; PART_NUMBER: 250-0419
C5 = CAP: CAP.,0.1uF,X7R,50V,10%,0603; CLASS: DISCRETE; Dielectric Type: X7R; FPLIST: CC0603N,CC0603L,CC0603M; Inventory Qty: 32681; Manufacturer: AVX; Manufacturer PN: 06035C104KAT2A; PART_NUMBER: 150-0102; Package Size: 0603; Rated Voltage: 50V; Tolerance: 10%
D3 = LED: LED,GREEN,WATERCLEAR,1206; CLASS: DISCRETE; FPLIST: LED_1206,LED-WURTH-WL-SMCW; Inventory Qty: 6134; Manufacturer: WURTH ELEKTRONIK; Manufacturer PN: 150120GS75000; PART_NUMBER: 270-0080; Package Type: 1206
D4 = LED: LED,RED,WATERCLEAR,1206; CLASS: DISCRETE; FPLIST: LED_1206,LED-WURTH-WL-SMCW; Inventory Qty: 3146; Manufacturer: WURTH ELEKTRONIK; Manufacturer PN: 150120RS75000; PART_NUMBER: 270-0078; Package Type: 1206
E7 = TESTPOINT_.219_MILL-MAX_2501: TEST POINT,TURRET,0.094" MTG. HOLE,PCB 0.062" THK; CLASS: IO; Inventory Qty: 416229; Manufacturer: MILL-MAX; Manufacturer PN: 2501-2-00-80-00-00-07-0; PART_FIELD_01: 3V3_BIAS; PART_NUMBER: 260-0003
E10 = TESTPOINT_.219_MILL-MAX_2501: TEST POINT,TURRET,0.094" MTG. HOLE,PCB 0.062" THK; CLASS: IO; Inventory Qty: 416229; Manufacturer: MILL-MAX; Manufacturer PN: 2501-2-00-80-00-00-07-0; PART_FIELD_01: ALERT; PART_NUMBER: 260-0003
E15 = TESTPOINT_.219_MILL-MAX_2501: TEST POINT,TURRET,0.094" MTG. HOLE,PCB 0.062" THK; CLASS: IO; Inventory Qty: 416229; Manufacturer: MILL-MAX; Manufacturer PN: 2501-2-00-80-00-00-07-0; PART_FIELD_01: SCL; PART_NUMBER: 260-0003
E44 = TESTPOINT_.219_MILL-MAX_2501: TEST POINT,TURRET,0.094" MTG. HOLE,PCB 0.062" THK; CLASS: IO; Inventory Qty: 416229; Manufacturer: MILL-MAX; Manufacturer PN: 2501-2-00-80-00-00-07-0; PART_FIELD_01: SDA; PART_NUMBER: 260-0003
J5 = CONN._FCI_12_POS_2MM: CONN.,HDR,SHROUDED,MALE,2x6,2mm,VERT,ST,THT; CLASS: IO; Inventory Qty: 13649; Manufacturer: FCI; Manufacturer PN: 98414-G06-12ULF; PART_NUMBER: 250-0433
J6 = PMBUS_HEADER: CONN.,HDR,FEMALE,2x4,2mm,R/A THT; CLASS: IO; Inventory Qty: 1242; Manufacturer: SULLINS CONNECTOR SOLUTIONS; Manufacturer PN: NPPN042FJFN-RC; PART_FIELD_01: DEMO HEADER (F); PART_NUMBER: 250-0750
J7 = PMBUS_HEADER: CONN.,HDR,MALE,2x4,2mm,R/A THT; CLASS: IO; Inventory Qty: 4992; Manufacturer: MOLEX; Manufacturer PN: 87760-0816; PART_FIELD_01: DEMO HEADER (M); PART_NUMBER: 250-0751
LB1 = BLANK_LABEL: LABEL SPEC, DEMO BOARD SERIAL NUMBER; Inventory Qty: 0; Manufacturer: BRADY; Manufacturer PN: THT-96-717-10; PART_NUMBER: 895-0154
MP1-MP4 = BLANK_PINLESS_MECHANICAL_PART: STANDOFF,NYLON,SNAP-ON,0.625 (5/8"),15.9mm; CLASS: DISCRETE; Inventory Qty: 141229; Manufacturer: KEYSTONE; Manufacturer PN: 8834; PART_NUMBER: 763-0013
PCB1 = BLANK_PCB_PART: BOM Notes: REV02; CLASS: DISCRETE; Inventory Qty: 0; Manufacturer: PHASE 3; Manufacturer PN: 600-DC2798A; PART_NUMBER: 600-DC2798A
Q9 = MOSFET_N-CH_D: XSTR.,MOSFET N-CH,60V,300mA,SOT-23; CLASS: DISCRETE; Inventory Qty: 7015; Manufacturer: VISHAY; Manufacturer PN: 2N7002K-T1-GE3; PART_NUMBER: 240-0125; Package Size: SOT-23; Package Type: SOT-23; Rated Voltage: 60V
Q10 = 3P_P-CH_TYPE1A: XSTR.,MOSFET, P-CH,20V,5.9A,TO-236 (SOT23-3); CLASS: DISCRETE; Inventory Qty: 19307; Manufacturer: VISHAY; Manufacturer PN: Si2365EDS-T1-GE3; PART_NUMBER: 240-0119; Package Size: SOT-23; Package Type: TO-236 (SOT23-3); Rated Voltage: 20V
R16 R197 = RES: RES.,4.99k OHMS,1%,1/10W,0603; CLASS: DISCRETE; FPLIST: CR0603N,CR0603L,CR0603M; Inventory Qty: 73409; Manufacturer: PANASONIC; Manufacturer PN: ERJ3EKF4991V; PART_NUMBER: 100-0121; Package Size: 0603; Rated Power: 1/10W; Temperature Coefficient: 100ppm/C; Tolerance: 1%
R27 = RES: RES.,200 OHMS,1%,1/10W,0603; CLASS: DISCRETE; FPLIST: CR0603N,CR0603L,CR0603M; Inventory Qty: 47444; Label: OPT 0; Manufacturer: VISHAY; Manufacturer PN: CRCW0603200RFKEA; PART_NUMBER: 100-0130; Package Size: 0603; Rated Power: 1/10W; Temperature Coefficient: 100ppm; Tolerance: 1%
R28 = RES: RES.,127 OHMS,1%,1/10W,0603,AEC-Q200; CLASS: DISCRETE; FPLIST: CR0603N,CR0603L,CR0603M; Inventory Qty: 81383; Label: OPT 0; Manufacturer: NIC; Manufacturer PN: NRC06F1270TRF; PART_NUMBER: 100-0054; Package Size: 0603; Rated Power: 1/10W; Temperature Coefficient: 100ppm/C; Tolerance: 1%
R196 = RES: RES., OPTION, 0603; 4TH PART FIELD: AAC,; CLASS: DISCRETE; FPLIST: CR0603N,CR0603L,CR0603M; PART_NUMBER: 100-2374; Package Size: 0603
STNCL1 = BLANK_STENCIL_PART: BOM Notes: REV02; CLASS: DISCRETE; Inventory Qty: 0; Manufacturer: LINEAR TECH.; Manufacturer PN: 830-DC2798A; PART_NUMBER: 830-DC2798A
U2 = 24LC025-I_ST_TSSOP-8: IC, MEMORY,EEPROM,2Kb (256x8),TSSOP-8,400kHz; CLASS: IC; Inventory Qty: 15938; Manufacturer: Microchip; PART_NUMBER: 380-0087; Package Size: TSSOP-8; Package Type: TSSOP-8

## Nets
3V3: E7.1 J5.5(LGKPWR) Q10.2(S) R27.1
GND_POWER: C1.2 C3.1 C5.2 C10.2 C11.2 C12.2 C24.2 C25.2 C26.2 C71.1 C77.1 C85.2 C86.2 C87.2 C88.2 C93.2 C94.1 C95.1 C107.2 C108.2 C109.2 C110.2 C111.2 C112.2 C113.2 C114.2 C115.1 C116.1 C120.1 C122.2 C123.2 C124.1 C125.2 C126.2 E1.1 E4.1 E6.1 J2.1 J4.1 J5.3(GND) J5.10(GND) J6.8(GND) J7.8(GND) Q3.1(S) Q3.2(S) Q3.3(S) Q4.1(S) Q4.2(S) Q4.3(S) Q7.1(S) Q7.2(S) Q7.3(S) Q8.1(S) Q8.2(S) Q8.3(S) Q9.2(SOURCE) R28.2 U1.23(PGND) U2.1(A0) U2.2(A1) U2.3(A2) U2.4(VSS) U2.7(WP)
GND_SIGNAL: C18.2 C20.2 C104.1 C105.1 C106.1 C117.1 C119.2 C121.2 D5.2(A) JP1.4 JP2.4 JP4.3 R184.2 R185.2 R186.2 R194.1 R199.1 R200.2 R201.1 U1.8(SGND) U1.37(SGND)
VIN: C1.1 C85.1 C86.1 C87.1 C94.2 C95.2 C115.2 C116.2 E3.1 J1.1 R14.2 R22.1 R37.2 R43.2 R188.2 R202.2
ALERT: E10.1 J5.6(ALERTB) J6.2(ALERTB) J7.2(ALERTB) Q10.1(G) R11.1 U1.31(~{ALERT})
AUXP: C5.1 J5.1(AUXP) J6.5(AUXP) J7.5(AUXP) R16.1 R197.1 U2.8(VCC)
BG0: Q3.4(G) Q4.4(G) U1.25(BG1)
BG1: Q7.4(G) Q8.4(G) U1.20(BG2)
BOOST0: R12.2 U1.26(BOOST1)
BOOST1: R38.2 U1.19(BOOST2)
CLKIN: E37.1 JP3.6 R196.1
CLKOUT: E22.1 U1.6(CLKOUT)
EESCL: J5.11(AUXSCL) R197.2 U2.6(SCL)
EESDA: J5.12(AUXSDA) R16.2 U2.5(SDA)
EXTVCC: C120.2 E40.1 U1.22(EXTVCC)
INTVCC: C3.2 C124.2 D1.2(A) D2.2(A) D6.2(A) E2.1 JP1.1 JP2.1 JP3.2 R11.2 R13.2 R15.2 R187.2 R192.2 R198.1 U1.21(INTVCC)
ISENSE0+: C13.1 C19.1 R20.2 R22.2 U1.2(SENSE1+)
ISENSE0-: C13.2 R19.2 R21.2 U1.3(SENSE1-)
ISENSE1+: C28.2 C35.1 R43.1 R47.1 U1.12(SENSE2+)
ISENSE1-: C28.1 R42.2 R44.2 U1.11(SENSE2-)
ITH: C20.1 R183.2 U1.14(ITH)
PGOOD: E42.1 Q9.1(GATE) R192.1 U1.16(PGOOD)
PLLIN/MODE: JP3.1 JP3.3 JP3.5 U1.7(PLLIN/MODE)
RUN: D5.1(C) E38.1 JP4.2 R201.2 R202.1 U1.9(RUN)
SCL: E15.1 J5.4(SCL) J6.4(SCL) J7.4(SCL) R13.1 U1.30(SCL)
SDA: E44.1 J5.2(SDA) J6.3(SDA) J7.3(SDA) R15.1 U1.29(SDA)
SW0: C9.2 L1.1 Q1.1(S) Q1.2(S) Q1.3(S) Q2.1(S) Q2.2(S) Q2.3(S) Q3.5(D) Q4.5(D) R19.1 R90.2 U1.28(SW1)
SW1: C23.2 L2.2 Q5.1(S) Q5.2(S) Q5.3(S) Q6.1(S) Q6.2(S) Q6.3(S) Q7.5(D) Q8.5(D) R42.1 R92.2 U1.17(SW2)
TG0: Q1.4(G) Q2.4(G) U1.27(TG1)
TG1: Q5.4(G) Q6.4(G) U1.18(TG2)
VBIAS: C105.2 E39.1 R188.1 U1.24(VBIAS)
VOUT0: C10.1 C11.1 C12.1 C24.1 C25.1 C26.1 C88.1 C93.1 C107.1 C108.1 C109.1 C110.1 C111.1 C112.1 C113.1 C114.1 C122.1 C123.1 C125.1 C126.1 J3.1 Q1.5(D) Q2.5(D) Q5.5(D) Q6.5(D) R17.1
VSENSE0+: C118.2 E5.1 R17.2 R193.2 U1.1(VOUT)
N20554791: C19.2 L1.2 R14.1 R20.1 R21.1
N20555079: C9.1 D1.1(C) R12.1
N20555212: C77.2 R92.1
N20555645: C23.1 D2.1(C) R38.1
N20555715: C71.2 R90.1
N20557438: C35.2 L2.1 R37.1 R44.1 R47.2
N20713842: C18.1 R183.1
N20721163: JP1.2 JP1.3 U1.15(ILIM)
N20723019: R186.1 U1.32(VOUT_CFG)
N20748782: C118.1 C121.1 R193.1 R194.2 U1.13(VFB)
N20750385: R187.1 R200.1 U1.4(FREQ)
N20751111: JP2.2 JP2.3 U1.5(PHASMD)
N20757935: D4.1(CATHODE) R28.1
N20757939: J6.1(CTRL) J7.1(CTRL)
N20757957: J6.6(UNUSED) J7.6(UNUSED) R196.2
N20757963: J6.7(UNUSED) J7.7(UNUSED)
N20758239: D4.2(ANODE) Q10.3(D)
N20802051: C106.2 U1.10(SS)
N20817648: D3.1(CATHODE) Q9.3(DRAIN)
N20875934: C117.2 D6.1(C) U1.36(VCCF)
N20886432: D3.2(ANODE) R27.2
N20890834: C119.1 R185.1 R199.2 U1.33(TSNS)
N20893039: R184.1 U1.35(ASEL)
N20893048: C104.2 U1.34(CSLEW)
N20961325: JP3.4 R198.2

Not connected (* = marked no-connect by the designer): J5 7(GPIO_1) 8(OUTEN_0) 9(OUTEN_1); JP4 1

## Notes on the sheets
sheet 1
- REVISION HISTORY
- ECO
- REV
- DESCRIPTION
- APPROVED
- DATE
- 2
- PRODUCTION
- XC
- 11-18-19
- R185 IS NTC
- NOTE: UNLESS OTHERWISE SPECIFIED
- BOOST CONTROLLER WITH PMBUS
- 1.  ALL RESISTORS AND CAPACITORS ARE 0603.
- 11-18-19
- NOTE:
  T1 - T8 ARE EXPOSED PCB VIAS
  FOR USE AS TEST POINTS
- NOTE:
  VOUT0 AND VOUT1 DEFAULT OUTPUT = 1.8V
- LTC3880EUJ - CURRENT MODE DUAL PHASE / DUAL CHANNEL
  STEP-DOWN CONTROLLER WITH I2C / PMBus INTERFACE
- MAKE ALL SENSE CONNECTIONS TO L1/L2
  AND R10/R16 DIFFERENTIAL AND KELVIN
sheet 2
- ALL PARTS ON THIS PAGE ARE FOR DEMO ONLY, NOT NEEDED IN CUSTOMER DESIGN
- TO DC1613A
- PCA ADDITIONAL PARTS
- BOOST CONTROLLER WITH PMBUS
- 11-18-19
